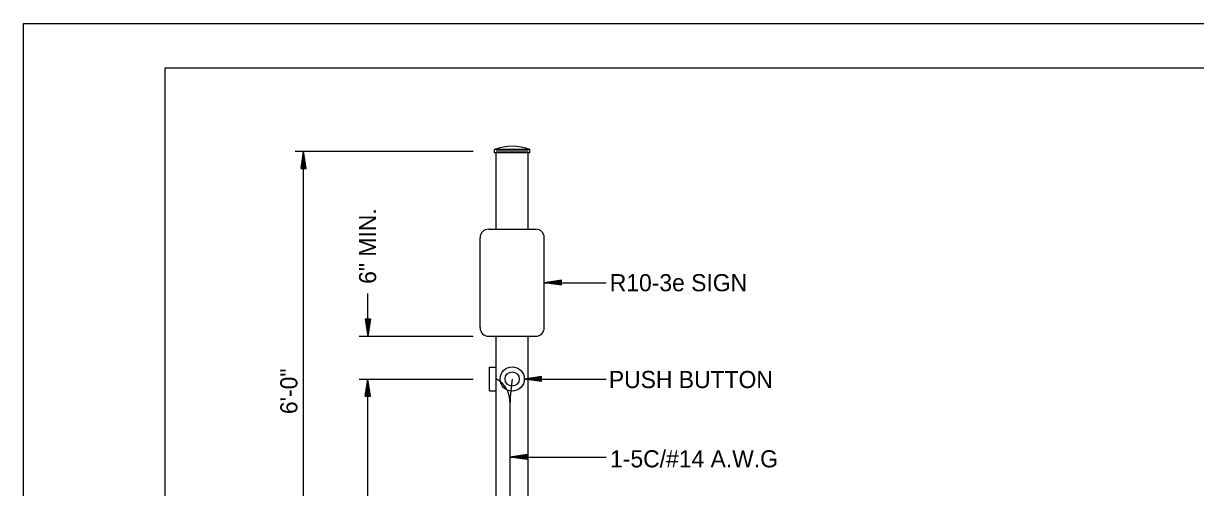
# Model space of a CAD drawing. Extents: x 1370050 to 1370716, y 380076 to 380502.
# Drawn here: x 1370049.7 to 1370255.2, y 380421.1 to 380502.4 of the extents above; entities that cross this region are included whole.
import ezdxf

# ---------------------------------------------------------------- set-up
doc = ezdxf.new("R2010")
doc.units = 0
for name, color, linetype in [('R_Border', 7, 'Continuous'), ('R_Grid', 7, 'Continuous'), ('R_No Plot', 7, 'Continuous')]:
    doc.layers.add(name, color=color, linetype=linetype)

msp = doc.modelspace()

# ---------------------------------------------------------------- linework, layer by layer
at = {"layer": 'R_Border'}
for p, q in [((1370074.49, 380494.58), (1370706.85, 380494.58)), ((1370074.49, 380083.66), (1370074.49, 380494.58))]:
    msp.add_line(p, q, dxfattribs=at)
at = {"layer": 'R_Grid'}
for p, q in [((1370097.29, 380479.98), (1370128.53, 380479.98)), ((1370098.34, 380476.98), (1370098.79, 380479.98)), ((1370098.42, 380476.98), (1370098.79, 380479.47)), ((1370098.5, 380476.98), (1370098.79, 380478.96)), ((1370098.57, 380476.98), (1370098.79, 380478.46)), ((1370098.79, 380387.58), (1370098.79, 380479.98)), ((1370099.24, 380476.98), (1370098.79, 380479.98)), ((1370099.17, 380476.98), (1370098.79, 380479.47)), ((1370099.09, 380476.98), (1370098.79, 380478.96)), ((1370099.02, 380476.98), (1370098.79, 380478.46)), ((1370138.47, 380480.28), (1370132.24, 380480.28)), ((1370132.24, 380479.68), (1370132.24, 380480.28)), ((1370138.47, 380479.68), (1370132.24, 380479.68)), ((1370138.17, 380479.98), (1370132.54, 380479.98)), ((1370132.54, 380466.33), (1370132.54, 380479.68)), ((1370138.17, 380466.33), (1370138.17, 380479.68)), ((1370138.47, 380479.68), (1370138.47, 380480.28)), ((1370098.34, 380476.98), (1370099.24, 380476.98)), ((1370098.65, 380476.98), (1370098.79, 380477.95)), ((1370098.72, 380476.98), (1370098.79, 380477.45)), ((1370098.94, 380476.98), (1370098.79, 380477.95)), ((1370098.86, 380476.98), (1370098.79, 380477.45)), ((1370131.23, 380466.33), (1370139.48, 380466.33)), ((1370129.73, 380449.08), (1370129.73, 380464.83)), ((1370140.98, 380449.08), (1370140.98, 380464.83)), ((1370143.98, 380457.4), (1370140.98, 380456.95)), ((1370140.98, 380456.95), (1370151.84, 380456.95)), ((1370143.98, 380456.5), (1370140.98, 380456.95)), ((1370143.98, 380457.33), (1370141.48, 380456.95)), ((1370143.98, 380456.58), (1370141.48, 380456.95)), ((1370143.98, 380457.25), (1370142, 380456.95)), ((1370143.98, 380456.65), (1370142, 380456.95)), ((1370143.98, 380457.18), (1370142.5, 380456.95)), ((1370143.98, 380456.73), (1370142.5, 380456.95)), ((1370143.98, 380457.1), (1370143.01, 380456.95)), ((1370143.98, 380456.81), (1370143.01, 380456.95)), ((1370143.98, 380457.02), (1370143.51, 380456.95)), ((1370143.98, 380456.88), (1370143.51, 380456.95)), ((1370143.98, 380456.5), (1370143.98, 380457.4)), ((1370110.04, 380447.58), (1370110.04, 380455.08)), ((1370109.59, 380450.58), (1370110.04, 380447.58)), ((1370110.49, 380450.58), (1370109.59, 380450.58)), ((1370109.67, 380450.58), (1370110.04, 380448.08)), ((1370109.75, 380450.58), (1370110.04, 380448.59)), ((1370109.82, 380450.58), (1370110.04, 380449.09)), ((1370109.9, 380450.58), (1370110.04, 380449.6)), ((1370109.97, 380450.58), (1370110.04, 380450.1)), ((1370110.49, 380450.58), (1370110.04, 380447.58)), ((1370110.19, 380450.58), (1370110.04, 380449.6)), ((1370110.34, 380450.58), (1370110.04, 380448.59)), ((1370110.42, 380450.58), (1370110.04, 380448.08)), ((1370110.27, 380450.58), (1370110.04, 380449.09)), ((1370110.11, 380450.58), (1370110.04, 380450.1)), ((1370108.54, 380447.58), (1370128.53, 380447.58)), ((1370131.23, 380447.58), (1370139.48, 380447.58)), ((1370132.54, 380389.98), (1370132.54, 380447.58)), ((1370138.17, 380389.98), (1370138.17, 380447.58)), ((1370131.39, 380442.18), (1370132.54, 380442.18)), ((1370131.39, 380437.98), (1370131.39, 380442.18)), ((1370108.54, 380440.08), (1370128.53, 380440.08)), ((1370109.59, 380437.08), (1370110.04, 380440.08)), ((1370109.67, 380437.08), (1370110.04, 380439.58)), ((1370110.04, 380387.58), (1370110.04, 380440.08)), ((1370110.49, 380437.08), (1370110.04, 380440.08)), ((1370110.42, 380437.08), (1370110.04, 380439.58)), ((1370140.48, 380440.53), (1370137.48, 380440.08)), ((1370137.48, 380440.08), (1370151.84, 380440.08)), ((1370140.48, 380439.63), (1370137.48, 380440.08)), ((1370140.48, 380440.45), (1370137.98, 380440.08)), ((1370140.48, 380439.7), (1370137.98, 380440.08)), ((1370140.48, 380440.38), (1370138.5, 380440.08)), ((1370140.48, 380439.78), (1370138.5, 380440.08)), ((1370140.48, 380440.3), (1370139, 380440.08)), ((1370140.48, 380439.85), (1370139, 380440.08)), ((1370140.48, 380440.22), (1370139.51, 380440.08)), ((1370140.48, 380439.93), (1370139.51, 380440.08)), ((1370140.48, 380440.15), (1370140.01, 380440.08)), ((1370140.48, 380440.01), (1370140.01, 380440.08)), ((1370140.48, 380439.63), (1370140.48, 380440.53)), ((1370109.75, 380437.08), (1370110.04, 380439.06)), ((1370109.82, 380437.08), (1370110.04, 380438.56)), ((1370109.9, 380437.08), (1370110.04, 380438.05)), ((1370109.97, 380437.08), (1370110.04, 380437.55)), ((1370110.34, 380437.08), (1370110.04, 380439.06)), ((1370110.27, 380437.08), (1370110.04, 380438.56)), ((1370110.19, 380437.08), (1370110.04, 380438.05)), ((1370110.11, 380437.08), (1370110.04, 380437.55)), ((1370131.39, 380437.98), (1370132.54, 380437.98)), ((1370109.59, 380437.08), (1370110.49, 380437.08)), ((1370134.98, 380369.94), (1370134.98, 380435.91)), ((1370137.98, 380426.86), (1370134.98, 380426.41)), ((1370134.98, 380426.41), (1370151.84, 380426.41)), ((1370137.98, 380425.96), (1370134.98, 380426.41)), ((1370137.98, 380426.78), (1370135.49, 380426.41)), ((1370137.98, 380426.03), (1370135.49, 380426.41)), ((1370137.98, 380426.71), (1370136, 380426.41)), ((1370137.98, 380426.11), (1370136, 380426.41)), ((1370137.98, 380426.63), (1370136.5, 380426.41)), ((1370137.98, 380426.18), (1370136.5, 380426.41)), ((1370137.98, 380426.55), (1370137.01, 380426.41)), ((1370137.98, 380426.26), (1370137.01, 380426.41)), ((1370137.98, 380426.48), (1370137.51, 380426.41)), ((1370137.98, 380426.34), (1370137.51, 380426.41)), ((1370137.98, 380425.96), (1370137.98, 380426.86))]:
    msp.add_line(p, q, dxfattribs=at)
for radius in [2.12, 1.25]:
    msp.add_circle((1370135.36, 380440.08), radius, dxfattribs=at)
for centre, radius, start, end in [((1370135.36, 380472.5), 8.37, 68.1777, 111.8223), ((1370131.23, 380464.83), 1.5, 90, 180), ((1370139.48, 380464.83), 1.5, 360, 90), ((1370131.23, 380449.08), 1.5, 180, 270), ((1370139.48, 380449.08), 1.5, 270, 0), ((1370130.38, 380436.02), 4.6, 358.6476, 61.9685), ((1370164.73, 380435.33), 29.75, 170.8268, 178.8957)]:
    msp.add_arc(centre, radius, start, end, dxfattribs=at)
at = {"layer": 'R_No Plot'}
msp.add_line((1370049.68, 380502.37), (1370716.35, 380502.37), dxfattribs=at)
msp.add_lwpolyline([(1370049.67, 380502.37), (1370716.35, 380502.37), (1370716.35, 380075.69), (1370049.67, 380075.69)], close=True, dxfattribs=at)

# ---------------------------------------------------------------- texts
at = {"layer": 'R_Grid'}
for s, p in [('6" MIN.', (1370111.51, 380456.75)), ('6\'-0"', (1370097.7, 380433.93))]:
    msp.add_text(s, height=3, rotation=90, dxfattribs=at).set_placement(p)
for s, p in [('R10-3e SIGN', (1370152.47, 380455.45)), ('PUSH BUTTON', (1370152.31, 380438.49)), ('1-5C/#14 A.W.G', (1370152.52, 380424.6))]:
    msp.add_text(s, height=3, dxfattribs=at).set_placement(p)

doc.saveas('drawing.dxf')
